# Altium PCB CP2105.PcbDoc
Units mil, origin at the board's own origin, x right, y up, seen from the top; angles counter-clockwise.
Board outline 990 x 600 mil, 2 copper layers (Top Layer, Bottom Layer), stack 65.792 mil thick; 17 components, 27 nets, 91 pads, 31 vias.
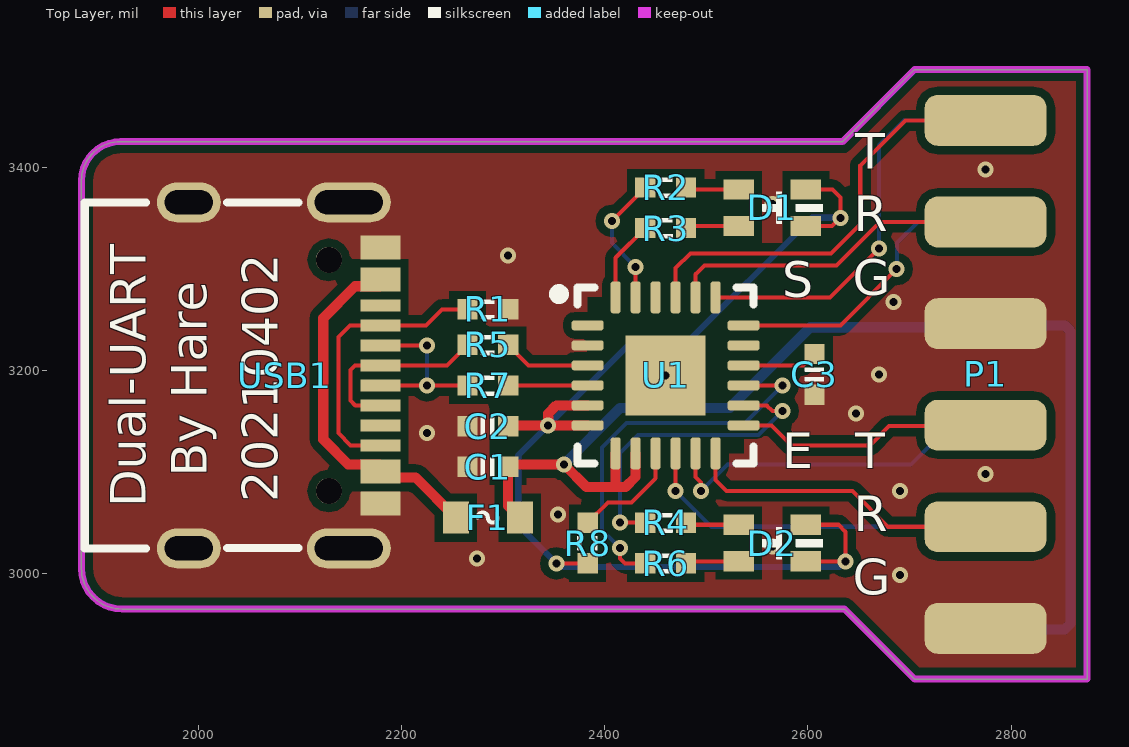
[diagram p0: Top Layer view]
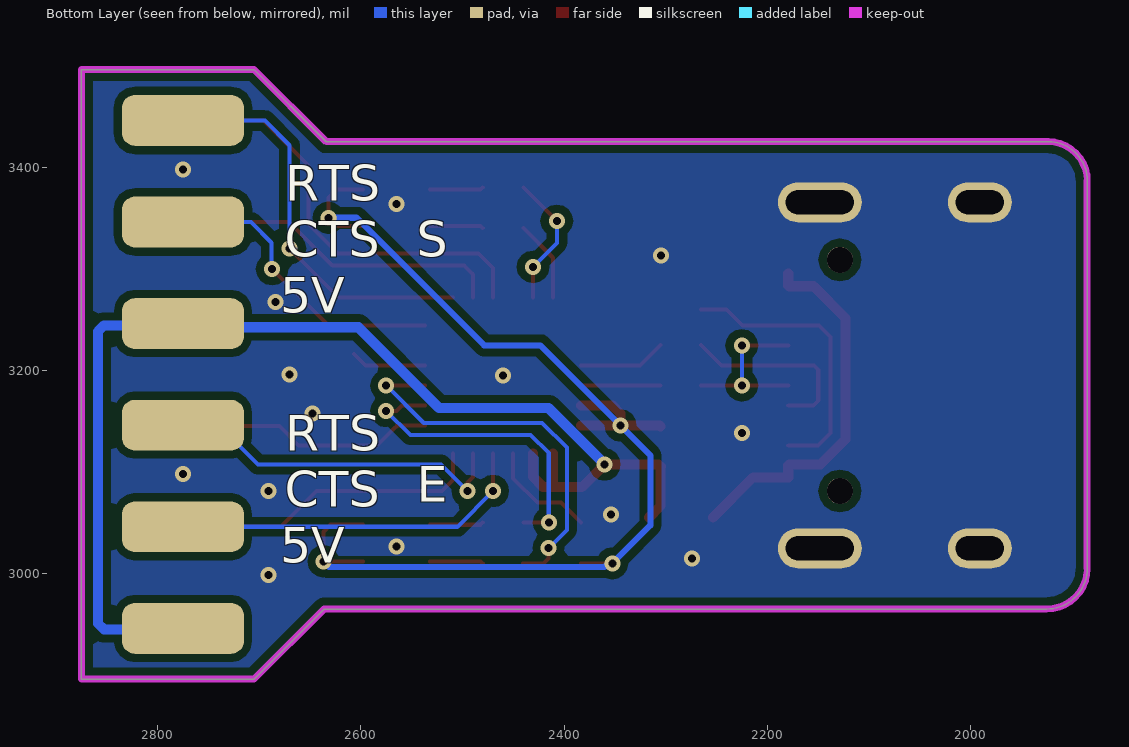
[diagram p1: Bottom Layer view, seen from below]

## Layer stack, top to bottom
Top Solder: solder mask 0.4, Solder Resist, Dk 3.5
Top Layer: signal copper 1.4
Dielectric 1: dielectric 62.9921, FR-4, Dk 4.8
Bottom Layer: signal copper 1.4
Bottom Solder: solder mask 0.4, Solder Resist, Dk 3.5

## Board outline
1925,2965 cw(c1925,3005) 1885,3005 1885,3386.65 cw(c1923.35,3386.65) 1923.35,3425 2634,3425 2705,3496 2875,3496 2875,2896 2705,2896 2636,2965

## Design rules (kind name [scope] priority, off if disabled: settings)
Clearance [All] p1: gap=7.87 ignorepadtopadclearanceinfootprint=TRUE
ComponentClearance [All] p1: gap=0 collisioncheckmode=3 verticalgap=0 showdistances=FALSE
DiffPairsRouting [All] p1: maxlimit=10 minlimit=10 mostfreqgap=10 toplayer_minwidth=7.87 toplayer_maxwidth=15 toplayer_prefwidth=7.87 bottomlayer_minwidth=7.87 bottomlayer_maxwidth=15 bottomlayer_prefwidth=7.87 maxuncoupledlength=500
MatchedLengths SD_CARD_MatchedLengths [InNetClass('SD_CARD')] p1: tolerance=400 checknetsindiffpair=FALSE checkdiffpairvsdiffpair=TRUE checkxsignals=TRUE checkothers=TRUE
PolygonConnect PolygonConnect_wifi [HasFootprint('RTL8723DU_MOUDLE')] p1: connectstyle=Relief reliefconductorwidth=10 reliefentries=4 polygonreliefangle="90 Angle" airgapwidth=10
PolygonConnect PolygonConnect_Res [HasFootprint('RES_0603')] p2: connectstyle=Relief reliefconductorwidth=10 reliefentries=4 polygonreliefangle="90 Angle" airgapwidth=10
PolygonConnect PolygonConnect_Core [HasFootprint('CORE-82PIN-SMD')] p3: connectstyle=Relief reliefconductorwidth=10 reliefentries=4 polygonreliefangle="90 Angle" airgapwidth=10
PolygonConnect [All] p4: connectstyle=Direct reliefconductorwidth=10 reliefentries=4 polygonreliefangle="90 Angle" airgapwidth=10
RoutingVias [All] p1: holewidth=28 width=50 viastyle="Through Hole" minholewidth=7.87 minwidth=15.75 maxholewidth=28 maxwidth=50
SolderMaskExpansion [All] p1: expansion=4
Width Width_PWR [InNetClass('PWR')] p1: maxlimit=23.62 minlimit=7.87 preferedwidth=10
Width [All] p2: maxlimit=23.62 minlimit=4 preferedwidth=8
28 further rules are at their usual default settings.

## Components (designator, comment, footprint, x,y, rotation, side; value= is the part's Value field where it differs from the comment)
C1 "4.7uF" CAP_0402 2285,3105 r180 top
C2 "4.7uF" CAP_0402 2285,3145 r180 top
C3 "4.7uF" CAP_0402 2606.5,3196 r270 top
D1 "=Value" LED_1616 2565,3360 r180 top
D2 "=Value" LED_1616 2565,3030 r180 top
F1 "MF-FSMF050X-2" FUSE_0603 2285,3055 r0 top
P1 "DIP 2x6" HDR2X6_2.54_180H 2775,3446 r0 top
R1 "5.1K" RES_0402 2285,3260 r180 top
R2 "4.7K" RES_0402 2460,3380 r0 top
R3 "1K" RES_0402 2460,3340 r0 top
R4 "4.7K" RES_0402 2460,3050 r0 top
R5 "22R" RES_0402 2285,3225 r180 top
R6 "1K" RES_0402 2460,3010 r0 top
R7 "22R" RES_0402 2285,3185 r180 top
R8 "10K" RES_0402 2383.23,3030 r90 top
U1 "CP2105" QFN-24-4.0X4.0-P0.5 2460,3195 r270 top
USB1 "Type-C" USB-Type-C 2085,3195 r180 top

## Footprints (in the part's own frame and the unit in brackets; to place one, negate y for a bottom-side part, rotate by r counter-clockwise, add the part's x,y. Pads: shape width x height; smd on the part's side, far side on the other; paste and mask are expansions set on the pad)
CAP_0402 [mil]
  rect 20x20 smd: 1(-20,0) 2(20,0)
  silkscreen extent -7,-9 7,9, body extent -20,-10 20,10, height 20
FUSE_0603 [mm]
  rect 0.65x0.8 smd: 1(-0.8,0) 2(0.8,0)
  silkscreen extent -0.25,-0.13 0.25,0.13, body extent -0.8,-0.4 0.8,0.4, height 0.45
HDR2X6_2.54_180H [mil]
  rrect50% 120x50 smd: 1(0,0) 3(0,-100) 5(0,-200) 7(0,-300) 9(0,-400) 11(0,-500)
  rrect50% 120x50 smd far side: 2(0,0) 4(0,-100) 6(0,-200) 8(0,-300) 10(0,-400) 12(0,-500)
  body extent -38,-550 415,50, height 78
LED_1616 [mil]
  rect 30x20 smd: 1(33,-18) 2(33,18) 3(-33,18) 4(-33,-18)
  silkscreen extent -50,-16 10,16, body extent -31,-30 31,30, height 13
QFN-24-4.0X4.0-P0.5 [mm] "QFN, 24-Leads, Body 4.00x4.00mm, Pitch 0.50mm, Thermal Pad 2.70x2.60mm, IPC Medium Density"
  rrect50% 0.25x0.8 smd: 1(-1.25,-1.95) 2(-0.75,-1.95) 3(-0.25,-1.95) 4(0.25,-1.95) 5(0.75,-1.95) 6(1.25,-1.95) 13(1.25,1.95) 14(0.75,1.95) 15(0.25,1.95) 16(-0.25,1.95) 17(-0.75,1.95) 18(-1.25,1.95)
  rrect50% 0.8x0.25 smd: 7(1.95,-1.25) 8(1.95,-0.75) 9(1.95,-0.25) 10(1.95,0.25) 11(1.95,0.75) 12(1.95,1.25) 19(-1.95,1.25) 20(-1.95,0.75) 21(-1.95,0.25) 22(-1.95,-0.25) 23(-1.95,-0.75) 24(-1.95,-1.25)
  rect 2x2 smd: 25(0,0)
  silkscreen extent -2.2,-2.79 2.2,2.2, body extent -2.07,-2.07 2.07,2.07, height 0.9
RES_0402 [mil]
  rect 20x20 smd: 1(-20,0) 2(20,0)
  silkscreen extent -7,-10 7,10, body extent -20,-10 20,10, height 14
USB-Type-C [mm]
  round 0.65 hole 0.65: 0(-1.105,2.89) 0(-1.105,-2.89)
  oval 1.6x1 hole 0.6 slot 1.2 at 0 deg: 1(2.395,4.325) 2(2.395,-4.325)
  oval 2.1x1 hole 0.6 slot 1.7 at 0 deg: 3(-1.605,-4.325) 4(-1.605,4.325)
  rect 1x0.3 smd: A1(-2.395,-3.35) A4(-2.395,-2.55) A5(-2.395,-1.25) A6(-2.395,-0.25) A7(-2.395,0.25) A8(-2.395,1.25) A9(-2.395,2.55) A12(-2.395,3.35) B1(-2.395,3.05) B4(-2.395,2.25) B5(-2.395,1.75) B6(-2.395,0.75) B7(-2.395,-0.75) B8(-2.395,-1.75) B9(-2.395,-2.25) B12(-2.395,-3.05)
  silkscreen extent -0.34,-4.33 4.99,4.33, body extent -2.67,-4.48 5.08,4.48, height 3.26

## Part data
C1 C2 C3: library part CAP, "Capacitor"
D1 D2: library part LEDx2, "LED˫ɫ", Value1=Green, Value2=Red
F1: library part Fuse, "Fuse"
P1: library part HDR2x6, "Header"
R1 R2 R3 R4 R5 R6 R7 R8: library part RES, "Resistor"
U1: "Single-Chip USB to Dual UART Data Transfer"
USB1: library part USB-Type-C

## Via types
v1: diameter 15.75, hole 7.87, Top Layer to Bottom Layer, tented both sides, 31 vias

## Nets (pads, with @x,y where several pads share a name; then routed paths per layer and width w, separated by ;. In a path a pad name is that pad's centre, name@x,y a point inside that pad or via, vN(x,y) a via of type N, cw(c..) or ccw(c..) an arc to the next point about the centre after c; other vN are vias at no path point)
CP_USB_D_N: R7.1 U1.4 | length 78.3
  Top Layer w4: R7.1 2305.16,3185.16 U1.4
CP_USB_D_P: R5.1 U1.3 | length 86.6
  Top Layer w4: R5.1 2325.16,3204.84 U1.3
ECI_CTS: P1.10 U1.10 | length 356.8
  Top Layer w4: v1(2469.84,3081.22) U1.10
  Bottom Layer w4: v1(2469.84,3081.22) 2505.06,3046 P1.10
ECI_RTS: P1.8 U1.11 | length 346.2
  Top Layer w4: U1.11 2489.53,3095 2495,3089.53 v1(2495,3081.22)
  Bottom Layer w4: v1(2495,3081.22) 2495,3081.32 2520.97,3107.29 2701.29,3107.29 2740,3146 P1.8
ECI_RX_LED: R4.1 U1.14 | length 311.2
  Top Layer w4: v1(2415,3050) R4.1 ; U1.14 2559.53,3165.47 2565,3160 v1(2575,3160)
  Bottom Layer w4: v1(2415,3050) 2415,3118.5 2432.78,3136.28 2551.28,3136.28 v1(2575,3160)
ECI_RXD: P1.9 U1.12 | length 311.1
  Top Layer w4: U1.12 2509.21,3092.11 2512.75,3088.57 2512.75,3088.47 2520,3081.22 2643.78,3081.22 2679,3046 P1.9
ECI_TX_LED: R6.1 U1.15 | length 385.2
  Top Layer w4: v1(2415.31,3025) 2415.31,3014.69 2420,3010 R6.1 R6.1@2440.31,3010 ; U1.15 2536.85,3185.08 2574.92,3185.08 v1(2575,3185)
  Bottom Layer w4: v1(2415.31,3025) 2414.9,3025 2397.25,3042.65 2397.25,3123.89 2421.52,3148.15 2538.05,3148.15 2574.9,3185 v1(2575,3185)
ECI_TXD: P1.7 U1.13 | length 254.6
  Top Layer w4: U1.13 2564.11,3145.79 2567.65,3142.25 2567.75,3142.25 2583.9,3126.1 2661.1,3126.1 2680,3145 2774,3145 P1.7
GND: C1.2 C2.2 C3.2 P1.5 P1.11 R1.1 U1.2 U1.25 USB1.1 USB1.2 USB1.3 USB1.4 USB1.A1 USB1.A12 USB1.B1 USB1.B12
  other v1: 2690.64,2998.65 2274.18,3014.69 2565,3026.5 2353.86,3058.07 2690.64,3081.32 2775,3097.72 2225,3138.18 2647.64,3157.42 2460,3195 2670,3196 2684.17,3267.12 2304.69,3312.94 2565,3363.5 2775,3397.87
NetC3_1: C3.1 U1.16 | length 74.3
  Top Layer w4: U1.16 2595.34,3204.84 C3.1
NetD1_1: D1.1 R2.2 | length 52.8
  Top Layer w4: R2.2 2482,3378 D1.1
NetD1_2: D1.2 R3.2 | length 52.8
  Top Layer w4: R3.2 2482,3342 D1.2
NetD2_1: D2.1 R4.2 | length 52.8
  Top Layer w4: R4.2 2482,3048 D2.1
NetD2_2: D2.2 R6.2 | length 52.8
  Top Layer w4: R6.2 2482,3012 D2.2
NetR1_2: R1.2 USB1.A5 USB1.B5 | length 279.5
  Top Layer w4: USB1.B5 2149.93,3126.1 2137.86,3138.18 2137.86,3232.86 2149.21,3244.21 USB1.A5 2224.21,3244.21 2240,3260 R1.2
NetR8_2: R8.2 U1.9 | length 109.5
  Top Layer w4: R8.2 2403.1,3069.87 2426.3,3069.87 2450.16,3093.73 U1.9
SCI_CTS: P1.4 U1.18 | length 295.4
  Top Layer w4: U1.18 2631.98,3244.21 v1(2687.31,3299.55)
  Bottom Layer w4: v1(2687.31,3299.55) 2687.75,3299.98 2687.75,3325.55 2708.2,3346 P1.4
SCI_RTS: P1.2 U1.19 | length 397.4
  Top Layer w4: U1.19 2621.77,3271.77 v1(2670,3320)
  Bottom Layer w4: v1(2670,3320) 2670,3421.51 2694.49,3446 P1.2
SCI_RX_LED: R2.1 U1.23 | length 131.6
  Top Layer w4: v1(2407.08,3347.09) R2.1 ; U1.23 v1(2430.47,3301.85)
  Bottom Layer w4: v1(2407.08,3347.09) 2407.08,3325.24 v1(2430.47,3301.85)
SCI_RXD: P1.3 U1.20 | length 329.5
  Top Layer w4: U1.20 2489.53,3294.53 2498.2,3303.2 2628.11,3303.2 2670.9,3346 P1.3
SCI_TX_LED: R3.1 U1.24 | length 80.3
  Top Layer w4: U1.24 2410.79,3310.79 R3.1
SCI_TXD: P1.1 U1.21 | length 428
  Top Layer w4: U1.21 2469.84,3300.63 2484.29,3315.08 2622.66,3315.08 2651.6,3344.02 2651.6,3401.6 2696,3446 P1.1
USB_D_N: R7.2 USB1.A7 USB1.B7 | length 170.9
  Top Layer w4: USB1.A7 v1(2225,3185.16) 2264.84,3185.16 R7.2 ; USB1.B7 v1(2225,3224.53)
  Bottom Layer w4: v1(2225,3185.16) v1(2225,3224.53)
USB_D_P: R5.2 USB1.A6 USB1.B6 | length 187.2
  Top Layer w4: USB1.B6 2154.53,3165.47 2149.73,3170.27 2149.73,3200.46 2154.12,3204.84 USB1.A6 2244.84,3204.84 R5.2
VBUS_5V: F1.1 USB1.A4 USB1.A9 USB1.B4 USB1.B9 | length 370.2
  Top Layer w10: USB1.A4 USB1.B9 2178.39,3282.68 2154.27,3282.68 2122.98,3251.39 2122.98,3132.02 2147.68,3107.32 2178.39,3107.32 USB1.B4 USB1.A9 2213.9,3094.61 F1.1
VCC_5V: C1.1 F1.2 P1.6 P1.12 U1.7 U1.8 | length 1184.8
  Top Layer w10: C1.1@2304.69,3105 2306.98,3107.29 v1(2360,3107.29) 2382.29,3085 2410.79,3085 ; C1.1 2305,3066.5 F1.2 ; U1.7 2410.79,3085 ; U1.8 2430.39,3118.15 2430.39,3095 2420.39,3085 2410.79,3085
  Bottom Layer w10: v1(2360,3107.29) 2360,3107.67 2415.36,3163.03 2523.16,3163.03 2602.51,3242.38 2771.38,3242.38 P1.6 2776.79,3244.21 2852.82,3244.21 2858.68,3238.35 2858.68,2950.86 2852.82,2945 2776,2945 P1.12
VCC_CP_3V45: C2.1 D1.3 D1.4 D2.3 D2.4 R8.1 U1.5 U1.6 | length 1193.2
  Top Layer w4: v1(2352.48,3010) R8.1 ; D2.3 v1(2636.89,3012) 2636.89,3041.08 2629.97,3048 D2.4 ; D1.3 2623.85,3342 v1(2631.97,3350.12) 2631.97,3370.27 2624.24,3378 D1.4
  Top Layer w10: C2.1 2305.71,3145.71 v1(2344.43,3145.71) ; U1.6 2383.15,3145.71 v1(2344.43,3145.71) ; U1.5 2352.48,3165.47 2344.43,3157.42 v1(2344.43,3145.71)
  Bottom Layer w6: v1(2631.97,3350.12) 2604.09,3350.12 2478.5,3224.53 2423.25,3224.53 v1(2344.43,3145.71) 2315,3116.28 2315,3047.48 v1(2352.48,3010) 2354.48,3012 2360.23,3006.25 2631.14,3006.25 v1(2636.89,3012)
pads on no net: U1.1 U1.17 U1.22 USB1.0 USB1.A8 USB1.B8

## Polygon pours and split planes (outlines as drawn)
GND on Top Layer "NONET_L-01_P-001" (solid, remove dead copper, pour order 2): 1810,3575 1855,3530 2930,3530 2930,2840 2875,2785 2825,2835 1795,2835
no net on Top Layer "NONET_L01_P000" (solid, remove dead copper, pour order 0): -1090.59,-350.01
GND on Bottom Layer "NONET_L-01_P-001" (solid, remove dead copper, pour order 4): 1770,3530 2885,3530 2930,3575 2940,3565 2940,2810 1825,2810 1790,2845

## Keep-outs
Keep-Out Layer:
  the board outline again, w6.89

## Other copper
Top Layer:
  pour cut-out: 2383.37,3271.77 2536.77,3271.77 2536.77,3118.23 2382.58,3118.23

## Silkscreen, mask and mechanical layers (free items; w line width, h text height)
Top Overlay:
  text "T" at 2646.66,3386.57 h60
  text "R" at 2645,3325 h60
  text "G" at 2644.08,3262.25 h60
  text "S" at 2575,3260 h60
  text "By Hare" at 2020,3095 h60 r90
  text "E" at 2575,3091.57 h60
  text "T" at 2646.66,3091.57 h60
  text "20210402" at 2090,3070 h60 r90
  text "Dual-UART" at 1960,3065 h60 r90
  text "R" at 2645,3030 h60
  text "G" at 2644.08,2967.25 h60
Bottom Overlay:
  text "RTS" at 2674.22,3355 h60
  text "S" at 2545,3300 h60
  text "CTS" at 2675,3300 h60
  text "5V" at 2679.52,3245 h60
  text "RTS" at 2674.22,3109 h60
  text "E" at 2545,3059 h60
  text "CTS" at 2675,3054 h60
  text "5V" at 2679.52,2999 h60
Mechanical 1:
  the board outline again, w6.89
Top Component:
  lines w6.89: 1885,3196 2880,3196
